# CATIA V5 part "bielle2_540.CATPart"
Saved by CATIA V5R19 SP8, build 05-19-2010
Part number: elt2
Bounding box of the stored display mesh (mm): x -19.996 to 19.996, y 0 to 20, z -120 to 119.988
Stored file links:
  D:\Dropbox\CIAO82010_JCF\VIGUIER\0540-VIGUIER\CAO\bielle2_540.CATPart
  D:\Dropbox\CIAO82010_JCF\VIGUIER\0540-VIGUIER\CAO\0540.CATProduct
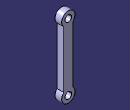
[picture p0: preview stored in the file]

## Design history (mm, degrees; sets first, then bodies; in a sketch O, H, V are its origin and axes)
Parameters
  longueur_bielles = 200 mm
External parameters (linked from other documents)
  External.rayon_assemblage = 10 mm
AxisSystem1: origin (0, 0, 0), X (1, 0, 0), Y (0, 1, 0), Z (0, 0, 1)
Body1 (main body)
  Sketch1 on ZX plane of AxisSystem1, origin (0, 0, 0), H (0, 0, 1), V (1, 0, 0)
    arc A1 centre (-100, 0) radius 20 from (-85.5724, 13.8508) to (-85.5724, -13.8508) ccw
    point P1 (-100, 0)
    point P2 (-85.5724, 13.8508)
    point P3 (-85.5724, -13.8508)
    arc A2 centre (100, 0) radius 20 from (85.5474, -13.8247) to (85.5474, 13.8247) ccw
    point P4 (100, 0)
    point P5 (85.5474, -13.8247)
    point P6 (85.5474, 13.8247)
    line L1 (-85.5724, 13.8508) -> (85.5474, 13.8247)
    line L2 (-85.5724, -13.8508) -> (85.5474, -13.8247)
    radius A2 = 20 {= 2*External.rayon_assemblage}
    radius A1 = 20 {= 2*External.rayon_assemblage}
    distance P4 P1 = 200 {= longueur_bielles}
    coincidence: P1 H, P4 H
    symmetry: P1 P4 V, P2 P3 H, P6 P5 H
  Pad1: profile Sketch1, direction (0, 1, 0), length 20
  Sketch2 on start face of Pad1, origin (0, 0, 0), H (1, 0, 0), V (0, 0, 1)
    circle A1 centre (0, 100) radius 10
    point P1 (0, 100)
    reference projected arc E1 centre (0, 100) radius 20 from (13.8247, 85.5474) to (-13.8247, 85.5474) ccw from edge [start face of Pad1 | face of Pad1 from Sketch1.A2]
    circle A2 centre (0, -100) radius 10
    radius A1 = 10 {= External.rayon_assemblage}
    coincidence: P1 V
    concentricity: P1 E1
    symmetry: A1 A2 H
  Pocket1: profile Sketch2, direction (0, 1, 0), through (limit type 3)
